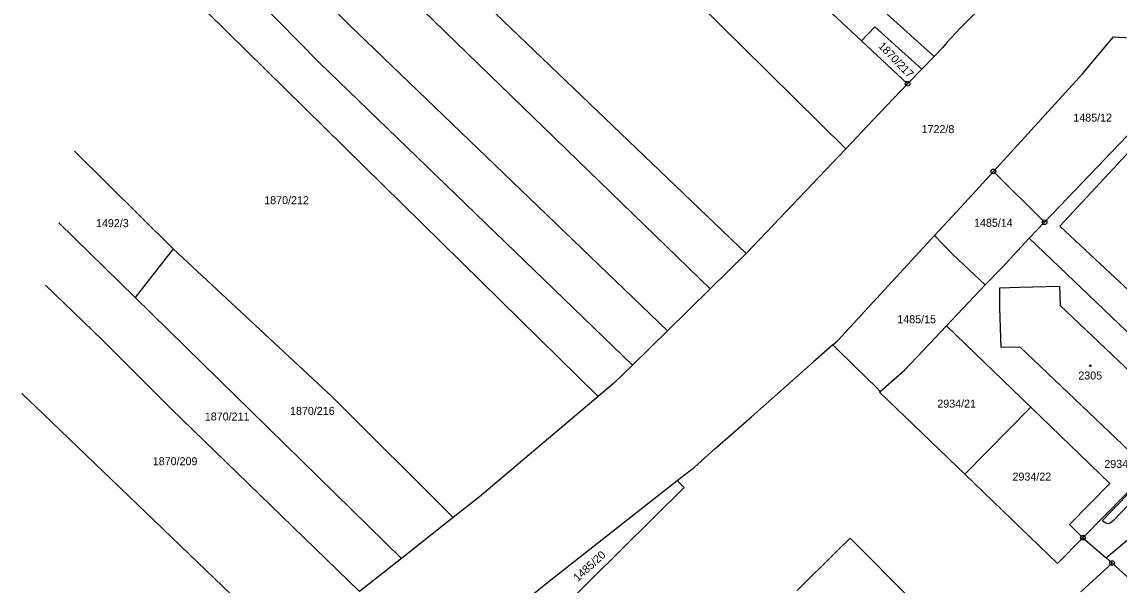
# Model space of a CAD drawing. Extents: x -779596 to -776743, y -1030330 to -1024513.
# Drawn here: x -779181.8 to -778948.7, y -1030114.3 to -1029994.5 of the extents above; entities that cross this region are included whole.
import ezdxf

# ---------------------------------------------------------------- set-up
doc = ezdxf.new("R2010")
doc.units = 0
for name, color, linetype in [('hranice parcel', 7, 'Continuous'), ('kultura', 7, 'Continuous'), ('Kód', 7, 'Continuous'), ('č_pacel stav_', 7, 'Continuous'), ('č_parcel poz_', 7, 'Continuous')]:
    doc.layers.add(name, color=color, linetype=linetype)

msp = doc.modelspace()

# ---------------------------------------------------------------- linework, layer by layer
at = {"layer": 'hranice parcel'}
for points in [[(-779077.96, -1029951.12), (-779006.74, -1030021.49)], [(-779112.32, -1029995.05), (-779155.53, -1029952.091)], [(-779118.66, -1030003.16), (-779153.53, -1029967.64)], [(-779059.38, -1030074.18), (-779159.11, -1029976.04)], [(-779113.03, -1029976.05), (-779035.56, -1030051.27)], [(-779027.89, -1030043.75), (-779097.91, -1029976.63)], [(-779020.97, -1029982.11), (-779003.45, -1029998.55)], [(-778982.54, -1029995.96), (-778974.92, -1029988.29)], [(-778988, -1030001.88), (-778998, -1029992.9)], [(-779112.32, -1029995.05), (-779044.65, -1030060.18)], [(-779003.45, -1029998.55), (-779000.58, -1029995.57)], [(-779000.58, -1029995.57), (-778990.59, -1030004.55)], [(-778982.54, -1029995.96), (-778985.27, -1029998.88)], [(-778956.47, -1030005.6), (-778949.86, -1029997.7)], [(-778949.86, -1029997.7), (-778942.75, -1029998.16)], [(-778993.64, -1030007.69), (-779003.45, -1029998.55)], [(-778988, -1030001.88), (-778986.17, -1030000)], [(-778985.27, -1029998.88), (-778986.17, -1030000)], [(-778990.59, -1030004.55), (-778988, -1030001.88)], [(-778964.53, -1030037.12), (-778931.05, -1030002.09)], [(-779118.66, -1030003.16), (-779052.1, -1030067.48)], [(-778990.59, -1030004.55), (-778993.64, -1030007.69)], [(-778975.4, -1030026.32), (-778956.47, -1030005.6)], [(-778993.64, -1030007.69), (-779000.91, -1030015.35)], [(-779000.91, -1030015.35), (-779006.74, -1030021.49)], [(-779006.74, -1030021.49), (-779027.89, -1030043.75)], [(-778961.29, -1030037.95), (-778944.31, -1030019.7)], [(-779170.656, -1030022.01), (-779149.66, -1030042.8)], [(-778975.4, -1030026.32), (-778982.24, -1030033.81)], [(-778975.4, -1030026.32), (-778964.53, -1030037.12)], [(-778987.91, -1030039.96), (-778982.24, -1030033.81)], [(-779157.72, -1030053.11), (-779173.945, -1030037.215)], [(-778967.77, -1030040.5), (-778964.53, -1030037.12)], [(-779008.48, -1030062.27), (-778987.91, -1030039.96)], [(-778987.91, -1030039.96), (-778984.01, -1030043.95)], [(-778951.55, -1030047), (-778961.29, -1030037.95)], [(-778967.77, -1030040.5), (-778973.51, -1030046.73)], [(-778967.77, -1030040.5), (-778929.6, -1030076.99)], [(-779149.66, -1030042.8), (-779157.72, -1030053.11)], [(-779149.66, -1030042.8), (-779115.92, -1030074.23)], [(-779027.89, -1030043.75), (-779035.56, -1030051.27)], [(-778984.01, -1030043.95), (-778977.17, -1030050.44)], [(-778973.51, -1030046.73), (-778977.17, -1030050.44)], [(-778929.68, -1030067.33), (-778951.55, -1030047)], [(-779176.821, -1030050.508), (-779164.78, -1030062.13)], [(-779035.56, -1030051.27), (-779044.65, -1030060.18)], [(-778977.17, -1030050.44), (-778985.38, -1030059.15)], [(-778974.02, -1030051.05), (-778969.82, -1030050.94)], [(-778974, -1030055.32), (-778974.02, -1030051.05)], [(-778969.82, -1030050.94), (-778961.32, -1030050.74)], [(-778961.32, -1030050.74), (-778961.22, -1030054.79)], [(-779157.72, -1030053.11), (-779101.17, -1030108.58)], [(-778973.74, -1030063.77), (-778974, -1030055.32)], [(-778961.22, -1030054.79), (-778937.88, -1030076.94)], [(-779044.65, -1030060.18), (-779052.1, -1030067.48)], [(-778985.38, -1030059.15), (-778989.04, -1030063.03)], [(-778985.38, -1030059.15), (-778967.42, -1030076.46)], [(-779164.78, -1030062.13), (-779150.19, -1030076.71)], [(-779009.53, -1030063.2), (-779013.6, -1030066.8)], [(-779009.53, -1030063.2), (-779008.48, -1030062.27)], [(-779009.53, -1030063.2), (-779004.58, -1030068.04)], [(-778989.04, -1030063.03), (-778994.21, -1030068.46)], [(-778969.68, -1030063.69), (-778973.74, -1030063.77)], [(-778946.42, -1030085.88), (-778969.68, -1030063.69)], [(-779052.1, -1030067.48), (-779056.13, -1030071.43)], [(-779019.36, -1030071.89), (-779013.6, -1030066.8)], [(-779004.58, -1030068.04), (-779000.24, -1030072.28)], [(-778999.42, -1030073.08), (-778994.21, -1030068.46)], [(-779056.13, -1030071.43), (-779059.38, -1030074.18)], [(-779026.8, -1030078.46), (-779019.36, -1030071.89)], [(-779000.24, -1030072.28), (-778999.42, -1030073.08)], [(-779177.24, -1030077.95), (-779181.802, -1030073.537)], [(-779115.92, -1030074.23), (-779090.15, -1030099.88)], [(-779059.38, -1030074.18), (-779084.58, -1030095.48)], [(-778999.42, -1030073.08), (-778999.58, -1030073.22)], [(-778999.58, -1030073.22), (-778981.45, -1030090.7)], [(-779150.19, -1030076.71), (-779110.07, -1030115.61)], [(-778981.45, -1030090.7), (-778967.42, -1030076.46)], [(-778967.42, -1030076.46), (-778950.63, -1030092.63)], [(-778956.39, -1030104.18), (-778929.6, -1030076.99)], [(-778952.32, -1030100.58), (-778929.6, -1030076.99)], [(-779177.24, -1030077.95), (-779128.18, -1030125.03)], [(-779034.57, -1030085.32), (-779026.8, -1030078.46)], [(-779038.92, -1030089.17), (-779034.57, -1030085.32)], [(-779042.57, -1030092.04), (-779038.92, -1030089.17)], [(-778937.99, -1030088.08), (-778949.8, -1030100.44)], [(-778981.45, -1030090.7), (-778961.78, -1030109.66)], [(-779069.8, -1030113.44), (-779042.57, -1030092.04)], [(-779041.09, -1030093.49), (-779067.61, -1030119.7)], [(-779042.57, -1030092.04), (-779041.09, -1030093.49)], [(-778950.63, -1030092.63), (-778959.24, -1030101.37)], [(-779084.58, -1030095.48), (-779090.15, -1030099.88)], [(-779090.15, -1030099.88), (-779101.17, -1030108.58)], [(-778951.52, -1030101.11), (-778952.32, -1030100.58)], [(-778949.8, -1030100.44), (-778950.37, -1030100.98)], [(-778959.24, -1030101.37), (-778956.39, -1030104.18)], [(-778950.97, -1030101.2), (-778951.52, -1030101.11)], [(-778951.47, -1030108.46), (-778944.21, -1030102.37)], [(-778950.37, -1030100.98), (-778950.97, -1030101.2)], [(-779008.78, -1030107.22), (-779005.83, -1030104.31)], [(-779005.83, -1030104.31), (-779003.03, -1030107.13)], [(-778961.78, -1030109.66), (-778956.39, -1030104.18)], [(-778956.39, -1030104.18), (-778951.47, -1030108.46)], [(-779017.08, -1030115.38), (-779008.78, -1030107.22)], [(-779003.03, -1030107.13), (-778988.13, -1030122.16)], [(-779101.17, -1030108.58), (-779110.07, -1030115.61)], [(-778950.19, -1030109.58), (-778956.79, -1030115.71)], [(-778951.47, -1030108.46), (-778950.19, -1030109.58)], [(-778950.19, -1030109.58), (-778934.85, -1030123.41)], [(-779073.8, -1030116.71), (-779069.8, -1030113.44)]]:
    msp.add_lwpolyline(points, dxfattribs=at)
at = {"layer": 'kultura'}
msp.add_circle((-778954.8, -1030067.64), 0.175, dxfattribs=at)
at = {"layer": 'Kód'}
for centre, radius in [((-778993.64, -1030007.69), 0.5), ((-778993.64, -1030007.69), 0.032), ((-778975.4, -1030026.32), 0.5), ((-778975.4, -1030026.32), 0.032), ((-778964.53, -1030037.12), 0.5), ((-778964.53, -1030037.12), 0.032), ((-778956.39, -1030104.18), 0.5), ((-778956.39, -1030104.18), 0.032), ((-778950.19, -1030109.58), 0.5), ((-778950.19, -1030109.58), 0.032)]:
    msp.add_circle(centre, radius, dxfattribs=at)

# ---------------------------------------------------------------- texts
at = {"layer": 'č_pacel stav_'}
msp.add_text('2305', height=1.7, dxfattribs=at).set_placement((-778957.35, -1030070.55))
at = {"layer": 'č_parcel poz_'}
for s, rotation, p in [('1870/217', 314.0025, (-778999.978, -1029999.784)), ('1485/20', 42.40034, (-779063.698, -1030113.608))]:
    msp.add_text(s, height=1.7, rotation=rotation, dxfattribs=at).set_placement(p)
for s, p in [('1485/12', (-778958.41, -1030015.73)), ('1722/8', (-778990.653, -1030018.17)), ('1870/212', (-779130.317, -1030033.28)), ('1492/3', (-779166.068, -1030038.161)), ('1485/14', (-778979.51, -1030038.09)), ('1485/15', (-778995.81, -1030058.58)), ('2934/21', (-778987.31, -1030076.53)), ('1870/211', (-779142.939, -1030079.266)), ('1870/216', (-779124.84, -1030078.07)), ('1870/209', (-779154, -1030088.772)), ('2934/3', (-778951.83, -1030089.34)), ('2934/22', (-778971.33, -1030092.04))]:
    msp.add_text(s, height=1.7, dxfattribs=at).set_placement(p)

doc.saveas('drawing.dxf')
